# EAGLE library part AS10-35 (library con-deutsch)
DEUTSCH Connector
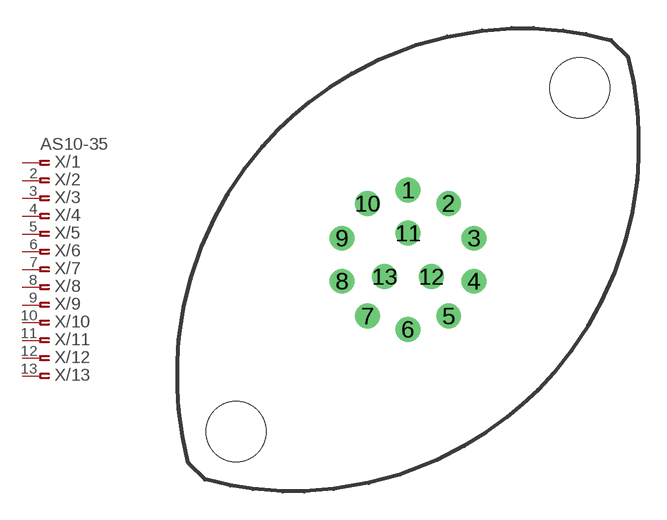
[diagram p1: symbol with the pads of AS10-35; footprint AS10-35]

Designator prefix X; gates /1=PINF_VAL /2=ASPINF /3=ASPINF /4=ASPINF /5=ASPINF /6=ASPINF /7=ASPINF /8=ASPINF /9=ASPINF /10=ASPINF /11=ASPINF /12=ASPINF /13=ASPINF

## AS10-35 (OC_FARNELL: unknown; OC_NEWARK: unknown)  [AS10-35]
1  /1:1  pas
2  /2:1  pas
3  /3:1  pas
4  /4:1  pas
5  /5:1  pas
6  /6:1  pas
7  /7:1  pas
8  /8:1  pas
9  /9:1  pas
10  /10:1  pas
11  /11:1  pas
12  /12:1  pas
13  /13:1  pas

## Footprint AS10-35 (pad centres in mm)
DEUTSCH Connector
drill 0.813 round: 1 0,3.708; 2 2.159,2.997; 3 3.505,1.143; 4 3.505,-1.143; 5 2.159,-2.997; 6 0,-3.708; 7 -2.159,-2.997; 8 -3.505,-1.143; 9 -3.505,1.143; 10 -2.159,2.997; 11 0,1.422; 12 1.245,-0.889; 13 -1.245,-0.889
hole 3.2 at 9.144,9.144
hole 3.2 at -9.144,-9.144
